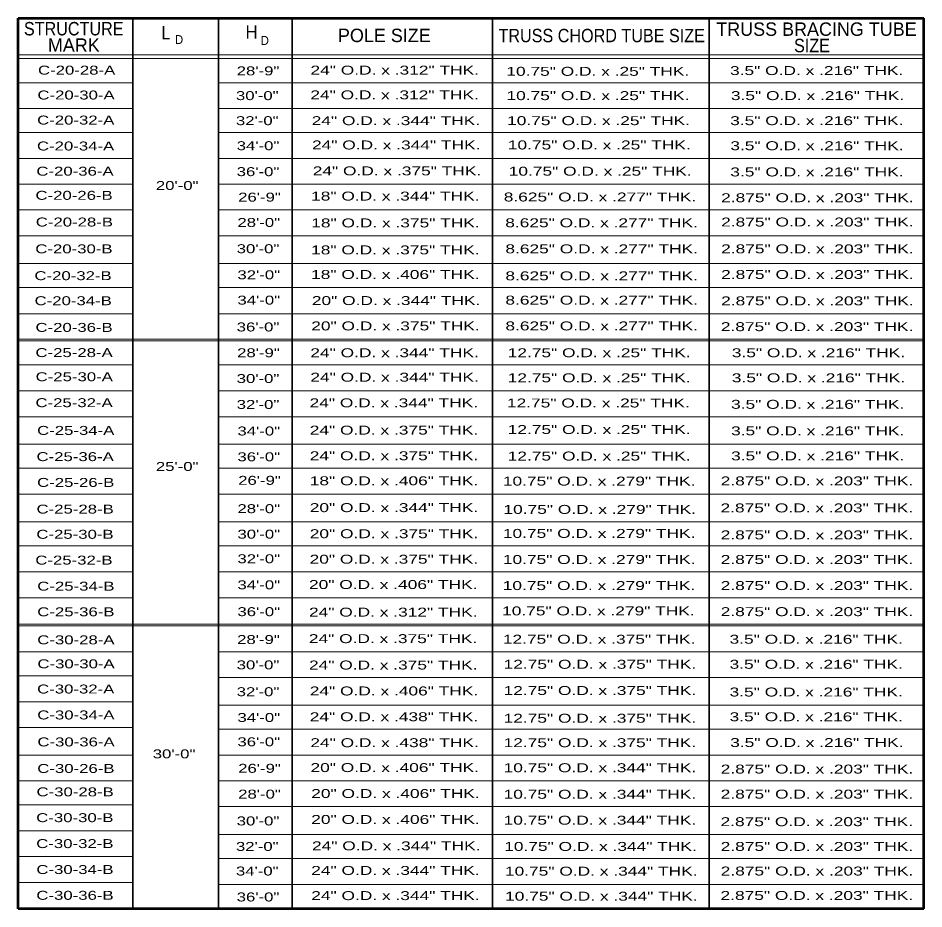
# Model space of a CAD drawing. Extents: x -34804.49 to -34794.67, y -181520.33 to -181510.37.
# Drawn here: x -34804.49 to -34798.41, y -181516.35 to -181510.37 of the extents above; entities that cross this region are included whole.
import ezdxf
from ezdxf.enums import TextEntityAlignment as Align

# ---------------------------------------------------------------- set-up
doc = ezdxf.new("R2010")
doc.units = 0
doc.header["$LTSCALE"] = 0.024
doc.layers.add('1', color=7, linetype='Continuous', lineweight=13)
doc.layers.add('13', color=7, linetype='Continuous', lineweight=25)

msp = doc.modelspace()

# ---------------------------------------------------------------- linework, layer by layer
at = {"layer": '1', "lineweight": 53}
for p, q in [((-34804.485, -181516.349), (-34804.485, -181510.373)), ((-34804.485, -181510.373), (-34798.41, -181510.373)), ((-34798.41, -181516.349), (-34798.41, -181510.373)), ((-34798.41, -181516.349), (-34804.485, -181516.349))]:
    msp.add_line(p, q, dxfattribs=at)
at = {"layer": '1', "lineweight": 35}
for p, q in [((-34803.716, -181516.349), (-34803.716, -181510.373)), ((-34803.141, -181516.349), (-34803.141, -181510.373)), ((-34802.647, -181516.349), (-34802.647, -181510.373)), ((-34801.303, -181516.349), (-34801.303, -181510.373)), ((-34799.85, -181510.373), (-34799.85, -181516.349))]:
    msp.add_line(p, q, dxfattribs=at)
at = {"layer": '1'}
for p, q in [((-34798.41, -181510.62), (-34804.485, -181510.62)), ((-34798.41, -181510.645), (-34804.485, -181510.645)), ((-34803.716, -181510.807), (-34804.485, -181510.807)), ((-34798.41, -181510.807), (-34803.141, -181510.807)), ((-34803.716, -181510.98), (-34804.485, -181510.98)), ((-34798.41, -181510.98), (-34803.141, -181510.98)), ((-34803.716, -181511.141), (-34804.485, -181511.141)), ((-34798.41, -181511.141), (-34803.141, -181511.141)), ((-34803.716, -181511.314), (-34804.485, -181511.314)), ((-34798.41, -181511.314), (-34803.141, -181511.314)), ((-34803.716, -181511.487), (-34804.485, -181511.487)), ((-34798.41, -181511.487), (-34803.141, -181511.487)), ((-34803.716, -181511.66), (-34804.485, -181511.66)), ((-34798.41, -181511.66), (-34803.141, -181511.66)), ((-34803.716, -181511.833), (-34804.485, -181511.833)), ((-34798.41, -181511.833), (-34803.141, -181511.833)), ((-34803.716, -181512.019), (-34804.485, -181512.019)), ((-34798.41, -181512.019), (-34803.141, -181512.019)), ((-34803.716, -181512.18), (-34804.485, -181512.18)), ((-34798.41, -181512.18), (-34803.141, -181512.18)), ((-34803.716, -181512.358), (-34804.485, -181512.358)), ((-34798.41, -181512.358), (-34803.141, -181512.358)), ((-34798.41, -181512.526), (-34804.485, -181512.526)), ((-34798.41, -181512.538), (-34804.485, -181512.538)), ((-34803.716, -181512.699), (-34804.485, -181512.699)), ((-34798.41, -181512.699), (-34803.141, -181512.699)), ((-34803.716, -181512.874), (-34804.485, -181512.874)), ((-34798.41, -181512.874), (-34803.141, -181512.874)), ((-34803.716, -181513.047), (-34804.485, -181513.047)), ((-34798.41, -181513.047), (-34803.141, -181513.047)), ((-34803.716, -181513.232), (-34804.485, -181513.232)), ((-34798.41, -181513.232), (-34803.141, -181513.232)), ((-34803.716, -181513.393), (-34804.485, -181513.393)), ((-34798.41, -181513.393), (-34803.141, -181513.393)), ((-34803.716, -181513.566), (-34804.485, -181513.566)), ((-34798.41, -181513.566), (-34803.141, -181513.566)), ((-34803.716, -181513.752), (-34804.485, -181513.752)), ((-34798.41, -181513.752), (-34803.141, -181513.752)), ((-34803.716, -181513.913), (-34804.485, -181513.913)), ((-34798.41, -181513.913), (-34803.141, -181513.913)), ((-34803.716, -181514.088), (-34804.485, -181514.088)), ((-34798.41, -181514.088), (-34803.141, -181514.088)), ((-34803.716, -181514.263), (-34804.485, -181514.263)), ((-34798.41, -181514.263), (-34803.141, -181514.263)), ((-34798.41, -181514.438), (-34804.485, -181514.438)), ((-34803.716, -181514.438), (-34804.485, -181514.438)), ((-34798.41, -181514.451), (-34804.485, -181514.451)), ((-34803.716, -181514.624), (-34804.485, -181514.624)), ((-34798.41, -181514.624), (-34803.141, -181514.624)), ((-34803.716, -181514.785), (-34804.485, -181514.785)), ((-34798.41, -181514.797), (-34803.141, -181514.797)), ((-34803.716, -181514.959), (-34804.485, -181514.959)), ((-34798.41, -181514.983), (-34803.141, -181514.983)), ((-34803.716, -181515.132), (-34804.485, -181515.132)), ((-34798.41, -181515.144), (-34803.141, -181515.144)), ((-34803.716, -181515.317), (-34804.485, -181515.317)), ((-34798.41, -181515.317), (-34803.141, -181515.317)), ((-34803.716, -181515.49), (-34804.485, -181515.49)), ((-34798.41, -181515.49), (-34803.141, -181515.49)), ((-34803.716, -181515.651), (-34804.485, -181515.651)), ((-34798.41, -181515.663), (-34803.141, -181515.663)), ((-34803.716, -181515.825), (-34804.485, -181515.825)), ((-34798.41, -181515.849), (-34803.141, -181515.849)), ((-34803.716, -181515.998), (-34804.485, -181515.998)), ((-34798.41, -181516.01), (-34803.141, -181516.01)), ((-34803.716, -181516.173), (-34804.485, -181516.173)), ((-34798.41, -181516.185), (-34803.141, -181516.185))]:
    msp.add_line(p, q, dxfattribs=at)

# ---------------------------------------------------------------- texts
at = {"layer": '13'}
for s, height, width, p in [('STRUCTURE', 0.09, 0.9, (-34804.112, -181510.489)), ('SIZE', 0.09004, 0.9, (-34799.1605, -181510.602)), ('C-20-28-A', 0.06, 1.4, (-34804.0925, -181510.752)), ('28\'-9"', 0.06, 1.4, (-34802.876, -181510.757)), ('24" O.D. x .312" THK.', 0.06, 1.45, (-34801.959, -181510.752)), ('10.75" O.D. x .25" THK.', 0.06, 1.45, (-34800.597, -181510.76)), ('3.5" O.D. x .216" THK.', 0.06, 1.45, (-34799.129, -181510.755)), ('C-20-30-A', 0.06, 1.4, (-34804.0965, -181510.919)), ('30\'-0"', 0.06, 1.4, (-34802.881, -181510.923)), ('24" O.D. x .312" THK.', 0.06, 1.45, (-34801.96, -181510.918)), ('10.75" O.D. x .25" THK.', 0.06, 1.45, (-34800.596, -181510.923)), ('3.5" O.D. x .216" THK.', 0.06, 1.45, (-34799.123, -181510.923)), ('C-20-32-A', 0.06, 1.4, (-34804.0985, -181511.087)), ('32\'-0"', 0.06, 1.4, (-34802.881, -181511.091)), ('24" O.D. x .344" THK.', 0.06, 1.45, (-34801.951, -181511.091)), ('10.75" O.D. x .25" THK.', 0.06, 1.45, (-34800.592, -181511.091)), ('3.5" O.D. x .216" THK.', 0.06, 1.45, (-34799.128, -181511.091)), ('C-20-34-A', 0.06, 1.4, (-34804.0995, -181511.261)), ('34\'-0"', 0.06, 1.4, (-34802.876, -181511.259)), ('24" O.D. x .344" THK.', 0.06, 1.45, (-34801.949, -181511.254)), ('10.75" O.D. x .25" THK.', 0.06, 1.45, (-34800.587, -181511.254)), ('3.5" O.D. x .216" THK.', 0.06, 1.45, (-34799.127, -181511.259)), ('C-20-36-A', 0.06, 1.4, (-34804.1035, -181511.43)), ('36\'-0"', 0.06, 1.4, (-34802.876, -181511.433)), ('24" O.D. x .375" THK.', 0.06, 1.45, (-34801.944, -181511.428)), ('10.75" O.D. x .25" THK.', 0.06, 1.45, (-34800.581, -181511.43)), ('3.5" O.D. x .216" THK.', 0.06, 1.45, (-34799.127, -181511.435)), ('20\'-0"', 0.06, 1.4, (-34803.418, -181511.526)), ('C-20-26-B', 0.06, 1.4, (-34804.1095, -181511.592)), ('26\'-9"', 0.06, 1.4, (-34802.866, -181511.604)), ('18" O.D. x .344" THK.', 0.06, 1.45, (-34801.955, -181511.597)), ('8.625" O.D. x .277" THK.', 0.06, 1.45, (-34800.582, -181511.603)), ('2.875" O.D. x .203" THK.', 0.06, 1.45, (-34799.124, -181511.608)), ('C-20-28-B', 0.06, 1.4, (-34804.1075, -181511.771)), ('28\'-0"', 0.06, 1.4, (-34802.871, -181511.774)), ('18" O.D. x .375" THK.', 0.06, 1.45, (-34801.954, -181511.777)), ('8.625" O.D. x .277" THK.', 0.06, 1.45, (-34800.572, -181511.776)), ('2.875" O.D. x .203" THK.', 0.06, 1.45, (-34799.124, -181511.771)), ('C-20-30-B', 0.06, 1.4, (-34804.1105, -181511.951)), ('30\'-0"', 0.06, 1.4, (-34802.876, -181511.95)), ('18" O.D. x .375" THK.', 0.06, 1.45, (-34801.955, -181511.958)), ('8.625" O.D. x .277" THK.', 0.06, 1.45, (-34800.571, -181511.951)), ('2.875" O.D. x .203" THK.', 0.06, 1.45, (-34799.124, -181511.951)), ('32\'-0"', 0.06, 1.4, (-34802.871, -181512.125)), ('18" O.D. x .406" THK.', 0.06, 1.45, (-34801.955, -181512.123)), ('2.875" O.D. x .203" THK.', 0.06, 1.45, (-34799.124, -181512.123)), ('C-20-32-B', 0.06, 1.4, (-34804.1165, -181512.131)), ('8.625" O.D. x .277" THK.', 0.06, 1.45, (-34800.571, -181512.132)), ('C-20-34-B', 0.06, 1.4, (-34804.1155, -181512.299)), ('34\'-0"', 0.06, 1.4, (-34802.871, -181512.295)), ('20" O.D. x .344" THK.', 0.06, 1.45, (-34801.95, -181512.298)), ('8.625" O.D. x .277" THK.', 0.06, 1.45, (-34800.571, -181512.295)), ('2.875" O.D. x .203" THK.', 0.06, 1.45, (-34799.124, -181512.3)), ('C-20-36-B', 0.06, 1.4, (-34804.1095, -181512.478)), ('36\'-0"', 0.06, 1.4, (-34802.876, -181512.475)), ('20" O.D. x .375" THK.', 0.06, 1.45, (-34801.954, -181512.468)), ('8.625" O.D. x .277" THK.', 0.06, 1.45, (-34800.571, -181512.468)), ('2.875" O.D. x .203" THK.', 0.06, 1.45, (-34799.126, -181512.473)), ('C-25-28-A', 0.06, 1.4, (-34804.1095, -181512.647)), ('28\'-9"', 0.06, 1.4, (-34802.873, -181512.648)), ('24" O.D. x .344" THK.', 0.06, 1.45, (-34801.96, -181512.648)), ('12.75" O.D. x .25" THK.', 0.06, 1.45, (-34800.588, -181512.648)), ('3.5" O.D. x .216" THK.', 0.06, 1.45, (-34799.117, -181512.648)), ('C-25-30-A', 0.06, 1.4, (-34804.1085, -181512.809)), ('30\'-0"', 0.06, 1.4, (-34802.876, -181512.821)), ('24" O.D. x .344" THK.', 0.06, 1.45, (-34801.96, -181512.812)), ('12.75" O.D. x .25" THK.', 0.06, 1.45, (-34800.588, -181512.816)), ('3.5" O.D. x .216" THK.', 0.06, 1.45, (-34799.117, -181512.816)), ('C-25-32-A', 0.06, 1.4, (-34804.1095, -181512.983)), ('32\'-0"', 0.06, 1.4, (-34802.876, -181512.995)), ('24" O.D. x .344" THK.', 0.06, 1.45, (-34801.965, -181512.984)), ('12.75" O.D. x .25" THK.', 0.06, 1.45, (-34800.593, -181512.985)), ('3.5" O.D. x .216" THK.', 0.06, 1.45, (-34799.122, -181512.994)), ('12.75" O.D. x .25" THK.', 0.06, 1.45, (-34800.588, -181513.163)), ('C-25-34-A', 0.06, 1.4, (-34804.0985, -181513.169)), ('34\'-0"', 0.06, 1.4, (-34802.871, -181513.173)), ('24" O.D. x .375" THK.', 0.06, 1.45, (-34801.964, -181513.167)), ('3.5" O.D. x .216" THK.', 0.06, 1.45, (-34799.122, -181513.172)), ('C-25-36-A', 0.06, 1.4, (-34804.1025, -181513.345)), ('24" O.D. x .375" THK.', 0.06, 1.45, (-34801.964, -181513.339)), ('12.75" O.D. x .25" THK.', 0.06, 1.45, (-34800.588, -181513.341)), ('3.5" O.D. x .216" THK.', 0.06, 1.45, (-34799.122, -181513.34)), ('36\'-0"', 0.06, 1.4, (-34802.871, -181513.346)), ('25\'-0"', 0.06, 1.4, (-34803.418, -181513.411)), ('C-25-26-B', 0.06, 1.4, (-34804.0985, -181513.518)), ('26\'-9"', 0.06, 1.4, (-34802.866, -181513.504)), ('18" O.D. x .406" THK.', 0.06, 1.45, (-34801.964, -181513.507)), ('10.75" O.D. x .279" THK.', 0.06, 1.45, (-34800.588, -181513.509)), ('2.875" O.D. x .203" THK.', 0.06, 1.45, (-34799.127, -181513.508)), ('C-25-28-B', 0.06, 1.4, (-34804.1025, -181513.697)), ('28\'-0"', 0.06, 1.4, (-34802.871, -181513.694)), ('20" O.D. x .344" THK.', 0.06, 1.45, (-34801.964, -181513.687)), ('10.75" O.D. x .279" THK.', 0.06, 1.45, (-34800.584, -181513.699)), ('2.875" O.D. x .203" THK.', 0.06, 1.45, (-34799.128, -181513.689)), ('C-25-30-B', 0.06, 1.4, (-34804.1035, -181513.866)), ('30\'-0"', 0.06, 1.4, (-34802.871, -181513.865)), ('20" O.D. x .375" THK.', 0.06, 1.45, (-34801.964, -181513.862)), ('10.75" O.D. x .279" THK.', 0.06, 1.45, (-34800.588, -181513.86)), ('2.875" O.D. x .203" THK.', 0.06, 1.45, (-34799.127, -181513.87)), ('C-25-32-B', 0.06, 1.4, (-34804.1105, -181514.039)), ('32\'-0"', 0.06, 1.4, (-34802.871, -181514.03)), ('20" O.D. x .375" THK.', 0.06, 1.45, (-34801.965, -181514.033)), ('10.75" O.D. x .279" THK.', 0.06, 1.45, (-34800.588, -181514.035)), ('2.875" O.D. x .203" THK.', 0.06, 1.45, (-34799.127, -181514.035)), ('C-25-34-B', 0.06, 1.4, (-34804.0975, -181514.214)), ('34\'-0"', 0.06, 1.4, (-34802.871, -181514.205)), ('20" O.D. x .406" THK.', 0.06, 1.45, (-34801.969, -181514.203)), ('10.75" O.D. x .279" THK.', 0.06, 1.45, (-34800.589, -181514.21)), ('2.875" O.D. x .203" THK.', 0.06, 1.45, (-34799.127, -181514.21)), ('C-25-36-B', 0.06, 1.4, (-34804.0975, -181514.386)), ('36\'-0"', 0.06, 1.4, (-34802.871, -181514.385)), ('24" O.D. x .312" THK.', 0.06, 1.45, (-34801.969, -181514.388)), ('10.75" O.D. x .279" THK.', 0.06, 1.45, (-34800.593, -181514.38)), ('2.875" O.D. x .203" THK.', 0.06, 1.45, (-34799.127, -181514.385)), ('C-30-28-A', 0.06, 1.4, (-34804.0975, -181514.574)), ('28\'-9"', 0.06, 1.4, (-34802.873, -181514.572)), ('24" O.D. x .375" THK.', 0.06, 1.45, (-34801.97, -181514.566)), ('12.75" O.D. x .375" THK.', 0.06, 1.45, (-34800.588, -181514.57)), ('3.5" O.D. x .216" THK.', 0.06, 1.45, (-34799.132, -181514.57)), ('C-30-30-A', 0.06, 1.4, (-34804.0965, -181514.735)), ('30\'-0"', 0.06, 1.4, (-34802.876, -181514.742)), ('12.75" O.D. x .375" THK.', 0.06, 1.45, (-34800.583, -181514.738)), ('3.5" O.D. x .216" THK.', 0.06, 1.45, (-34799.132, -181514.738)), ('24" O.D. x .375" THK.', 0.06, 1.45, (-34801.969, -181514.743)), ('C-30-32-A', 0.06, 1.4, (-34804.0985, -181514.904)), ('32\'-0"', 0.06, 1.4, (-34802.876, -181514.922)), ('24" O.D. x .406" THK.', 0.06, 1.45, (-34801.964, -181514.917)), ('12.75" O.D. x .375" THK.', 0.06, 1.45, (-34800.583, -181514.914)), ('3.5" O.D. x .216" THK.', 0.06, 1.45, (-34799.132, -181514.924)), ('C-30-34-A', 0.06, 1.4, (-34804.0975, -181515.078)), ('34\'-0"', 0.06, 1.4, (-34802.871, -181515.095)), ('24" O.D. x .438" THK.', 0.06, 1.45, (-34801.964, -181515.09)), ('12.75" O.D. x .375" THK.', 0.06, 1.45, (-34800.583, -181515.1)), ('3.5" O.D. x .216" THK.', 0.06, 1.45, (-34799.132, -181515.09)), ('C-30-36-A', 0.06, 1.4, (-34804.0965, -181515.259)), ('36\'-0"', 0.06, 1.4, (-34802.871, -181515.258)), ('24" O.D. x .438" THK.', 0.06, 1.45, (-34801.96, -181515.264)), ('12.75" O.D. x .375" THK.', 0.06, 1.45, (-34800.583, -181515.264)), ('3.5" O.D. x .216" THK.', 0.06, 1.45, (-34799.128, -181515.263)), ('30\'-0"', 0.06, 1.4, (-34803.439, -181515.339)), ('C-30-26-B', 0.06, 1.4, (-34804.0975, -181515.437)), ('26\'-9"', 0.06, 1.4, (-34802.866, -181515.436)), ('20" O.D. x .406" THK.', 0.06, 1.45, (-34801.959, -181515.431)), ('10.75" O.D. x .344" THK.', 0.06, 1.45, (-34800.583, -181515.432)), ('2.875" O.D. x .203" THK.', 0.06, 1.45, (-34799.127, -181515.441)), ('C-30-28-B', 0.06, 1.4, (-34804.1025, -181515.594)), ('28\'-0"', 0.06, 1.4, (-34802.866, -181515.609)), ('20" O.D. x .406" THK.', 0.06, 1.45, (-34801.954, -181515.605)), ('10.75" O.D. x .344" THK.', 0.06, 1.45, (-34800.583, -181515.61)), ('2.875" O.D. x .203" THK.', 0.06, 1.45, (-34799.127, -181515.609)), ('C-30-30-B', 0.06, 1.4, (-34804.1045, -181515.767)), ('30\'-0"', 0.06, 1.4, (-34802.876, -181515.789)), ('20" O.D. x .406" THK.', 0.06, 1.45, (-34801.954, -181515.779)), ('10.75" O.D. x .344" THK.', 0.06, 1.45, (-34800.583, -181515.784)), ('2.875" O.D. x .203" THK.', 0.06, 1.45, (-34799.128, -181515.794)), ('C-30-32-B', 0.06, 1.4, (-34804.1045, -181515.941)), ('24" O.D. x .344" THK.', 0.06, 1.45, (-34801.949, -181515.956)), ('32\'-0"', 0.06, 1.4, (-34802.881, -181515.96)), ('10.75" O.D. x .344" THK.', 0.06, 1.45, (-34800.579, -181515.96)), ('2.875" O.D. x .203" THK.', 0.06, 1.45, (-34799.127, -181515.96)), ('C-30-34-B', 0.06, 1.4, (-34804.1035, -181516.115)), ('34\'-0"', 0.06, 1.4, (-34802.881, -181516.125)), ('24" O.D. x .344" THK.', 0.06, 1.45, (-34801.954, -181516.121)), ('10.75" O.D. x .344" THK.', 0.06, 1.45, (-34800.574, -181516.126)), ('2.875" O.D. x .203" THK.', 0.06, 1.45, (-34799.127, -181516.125)), ('C-30-36-B', 0.06, 1.4, (-34804.1035, -181516.288)), ('36\'-0"', 0.06, 1.4, (-34802.876, -181516.299)), ('24" O.D. x .344" THK.', 0.06, 1.45, (-34801.954, -181516.29)), ('10.75" O.D. x .344" THK.', 0.06, 1.45, (-34800.573, -181516.294)), ('2.875" O.D. x .203" THK.', 0.06, 1.45, (-34799.128, -181516.289))]:
    msp.add_text(s, height=height, dxfattribs=dict(at, width=width)).set_placement(p, align=Align.CENTER)
for s, height, width, p in [('L', 0.09, 0.85, (-34803.523, -181510.516)), ('H', 0.09, 0.95, (-34802.96, -181510.511)), ('D', 0.06, 0.95, (-34803.433, -181510.547)), ('TRUSS CHORD TUBE SIZE', 0.09, 0.9, (-34801.263, -181510.535)), ('D', 0.06, 0.95, (-34802.858, -181510.553))]:
    msp.add_text(s, height=height, dxfattribs=dict(at, width=width)).set_placement(p)
for s, p in [('TRUSS BRACING TUBE', (-34799.1305, -181510.492)), ('MARK', (-34804.1115, -181510.599))]:
    msp.add_text(s, height=0.09, dxfattribs=at).set_placement(p, align=Align.CENTER)
msp.add_text('POLE SIZE', height=0.09004, dxfattribs=at).set_placement((-34802.34, -181510.534))

doc.saveas('drawing.dxf')
